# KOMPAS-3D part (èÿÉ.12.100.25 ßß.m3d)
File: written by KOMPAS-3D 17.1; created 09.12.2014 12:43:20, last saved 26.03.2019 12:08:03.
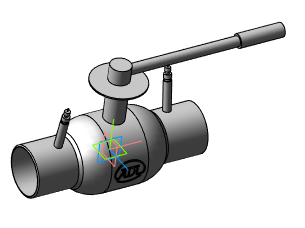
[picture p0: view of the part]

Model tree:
1. Операция без истории:8  (labels: Сталь 20  ГОСТ 1050-88)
